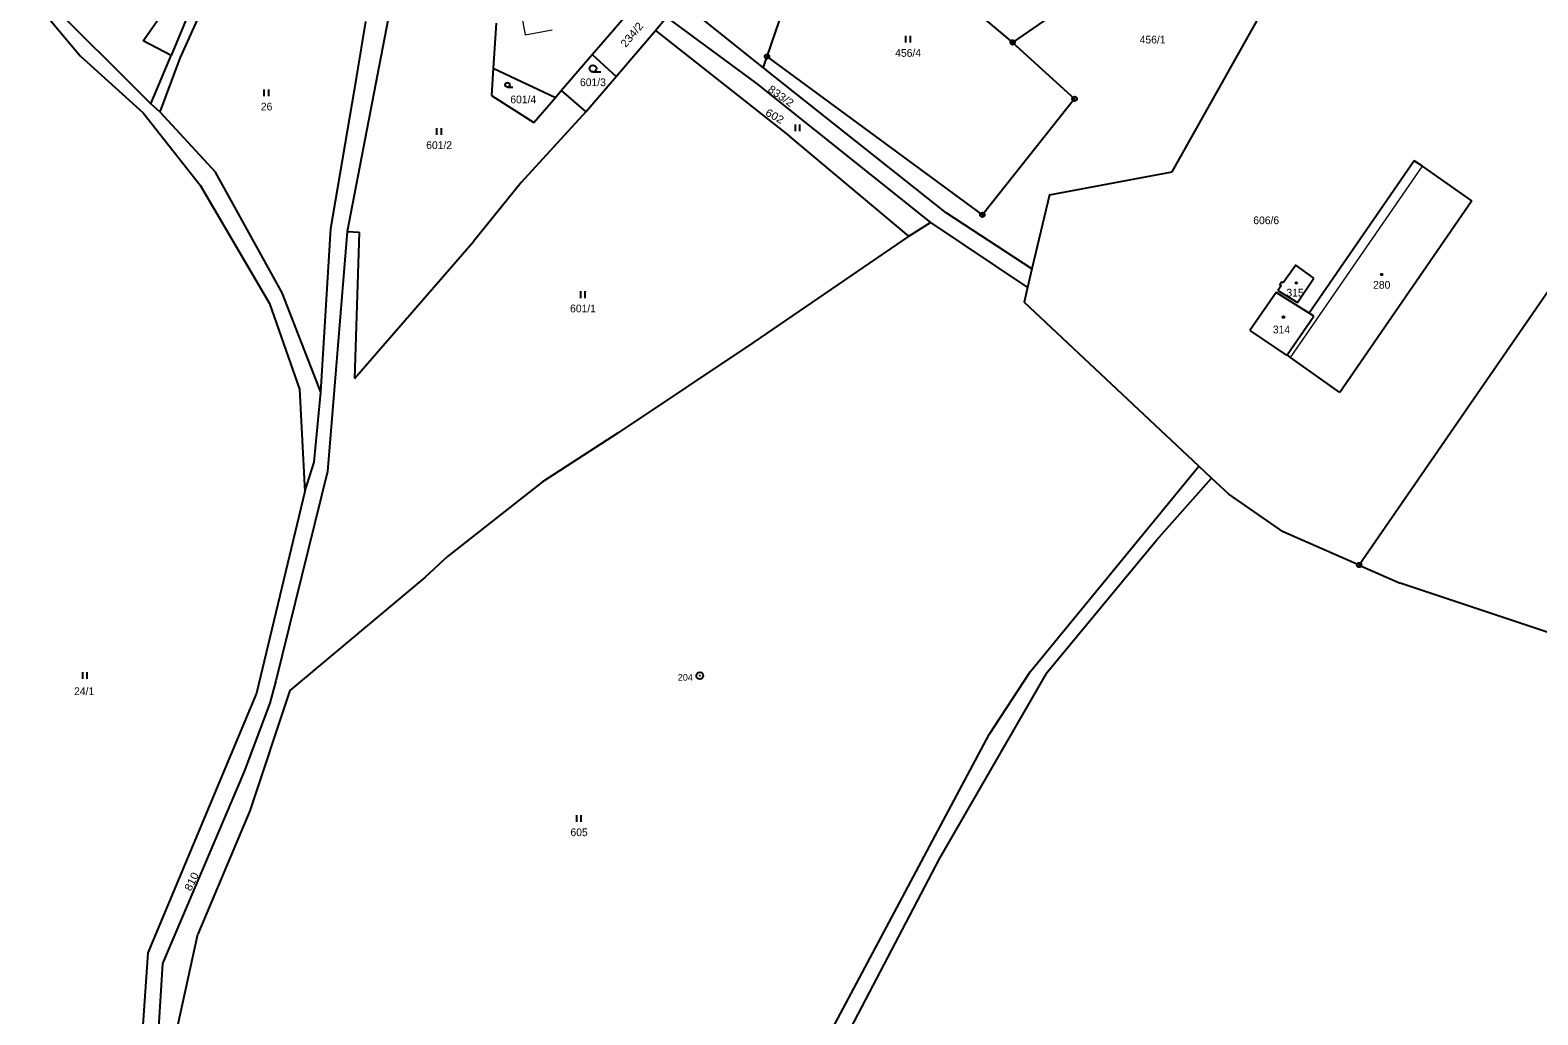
# Model space of a CAD drawing. Extents: x -739410 to -735662, y -942282 to -940043.
# Drawn here: x -737930.6 to -737598.7, y -941824.2 to -941607.4 of the extents above; entities that cross this region are included whole.
import ezdxf
from ezdxf.enums import TextEntityAlignment as Align

# ---------------------------------------------------------------- set-up
doc = ezdxf.new("R2010")
doc.units = 0
doc.header["$LTSCALE"] = 0.68
for name, color, linetype, lineweight in [('1', 7, 'Continuous', 25), ('3', 7, 'Continuous', 25), ('4', 7, 'Continuous', 13), ('5', 7, 'Continuous', 25), ('8', 7, 'Continuous', 25)]:
    doc.layers.add(name, color=color, linetype=linetype, lineweight=lineweight)
doc.layers.add('2', color=7, linetype='Continuous')

msp = doc.modelspace()

# ---------------------------------------------------------------- linework, layer by layer
at = {"layer": '1'}
for p, q in [((-737768.36, -941613.19), (-737755.48, -941575.64)), ((-737755.48, -941575.64), (-737714.29, -941610.09)), ((-737809.88, -941583.11), (-737769.2, -941615.65)), ((-737679.14, -941638.6), (-737649.53, -941585.72)), ((-737682.31, -941587.99), (-737714.29, -941610.09)), ((-737890.94, -941592.16), (-737899.54, -941612.96)), ((-737928.35, -941599.28), (-737904.01, -941623.61)), ((-737890.07, -941596.74), (-737897.59, -941613.54)), ((-737930.57, -941599.84), (-737919.54, -941613.02)), ((-737905.69, -941609.73), (-737899.64, -941601.14)), ((-737851.42, -941603.01), (-737860.8, -941651.75)), ((-737806.88, -941612.78), (-737795.94, -941600.02)), ((-737858.65, -941617.55), (-737856.7, -941605.45)), ((-737827.98, -941605.86), (-737828.62, -941615.79)), ((-737792.88, -941607.48), (-737790.48, -941604.55)), ((-737790.48, -941604.55), (-737770.69, -941619.12)), ((-737801.56, -941617.59), (-737792.88, -941607.48)), ((-737792.88, -941607.48), (-737763.4, -941630.76)), ((-737899.54, -941612.96), (-737905.69, -941609.73)), ((-737904.01, -941623.61), (-737899.54, -941612.96)), ((-737813.65, -941620.67), (-737806.88, -941612.78)), ((-737806.88, -941612.78), (-737801.56, -941617.59)), ((-737714.29, -941610.09), (-737700.65, -941622.51)), ((-737919.54, -941613.02), (-737905.67, -941625.62)), ((-737897.59, -941613.54), (-737902.03, -941625.36)), ((-737828.62, -941615.79), (-737829.01, -941621.79)), ((-737828.62, -941615.79), (-737814.95, -941622.19)), ((-737769.2, -941615.65), (-737768.36, -941613.19)), ((-737769.2, -941615.65), (-737768.71, -941616.05)), ((-737728.94, -941647.58), (-737768.71, -941616.05)), ((-737720.95, -941648.06), (-737768.36, -941613.19)), ((-737864.41, -941651.03), (-737858.65, -941617.55)), ((-737808.26, -941625.37), (-737801.56, -941617.59)), ((-737770.69, -941619.12), (-737732.37, -941649.74)), ((-737829.01, -941621.79), (-737819.72, -941627.75)), ((-737819.72, -941627.75), (-737814.95, -941622.19)), ((-737814.95, -941622.19), (-737813.65, -941620.67)), ((-737813.65, -941620.67), (-737808.26, -941625.37)), ((-737700.65, -941622.51), (-737720.95, -941648.06)), ((-737905.67, -941625.62), (-737893.12, -941641.52)), ((-737902.03, -941625.36), (-737904.01, -941623.61)), ((-737902.03, -941625.36), (-737889.8, -941638.62)), ((-737808.26, -941625.37), (-737822.51, -941640.93)), ((-737737.12, -941652.71), (-737763.4, -941630.76)), ((-737625.86, -941636.15), (-737648.99, -941669.73)), ((-737624.09, -941637.33), (-737625.86, -941636.15)), ((-737875.06, -941665.19), (-737889.8, -941638.62)), ((-737706.2, -941643.64), (-737679.14, -941638.6)), ((-737613.18, -941644.99), (-737624.09, -941637.33)), ((-737893.12, -941641.52), (-737877.89, -941667.56)), ((-737822.51, -941640.93), (-737832.97, -941653.89)), ((-737579.37, -941640.18), (-737637.99, -941725.15)), ((-737706.2, -941643.64), (-737710.06, -941659.94)), ((-737613.18, -941644.99), (-737642.24, -941687.17)), ((-737710.06, -941659.94), (-737728.94, -941647.58)), ((-737866.56, -941687.07), (-737864.41, -941651.03)), ((-737860.8, -941651.75), (-737865.1, -941704.55)), ((-737860.8, -941651.75), (-737858.16, -941651.85)), ((-737858.16, -941651.85), (-737859.14, -941684.08)), ((-737737.12, -941652.71), (-737771.29, -941676.08)), ((-737737.12, -941652.71), (-737732.37, -941649.74)), ((-737732.37, -941649.74), (-737711.02, -941664.04)), ((-737859.14, -941684.08), (-737832.97, -941653.89)), ((-737710.06, -941659.94), (-737711.02, -941664.04)), ((-737651.61, -941667.37), (-737647.95, -941661.97)), ((-737866.56, -941687.07), (-737875.06, -941665.19)), ((-737711.02, -941664.04), (-737711.75, -941667.31)), ((-737656.28, -941665.13), (-737662.08, -941673.54)), ((-737648.99, -941669.73), (-737656.28, -941665.13)), ((-737655.87, -941664.7), (-737651.61, -941667.37)), ((-737654.72, -941663.01), (-737655.05, -941662.78)), ((-737877.89, -941667.56), (-737871.25, -941686.4)), ((-737673.26, -941703.38), (-737711.75, -941667.31)), ((-737647.96, -941670.38), (-737648.99, -941669.73)), ((-737662.08, -941673.54), (-737653.96, -941679.05)), ((-737771.29, -941676.08), (-737801.12, -941696.06)), ((-737653.1, -941679.44), (-737653.86, -941678.9)), ((-737642.24, -941687.17), (-737653.1, -941679.44)), ((-737871.25, -941686.4), (-737870.08, -941708.95)), ((-737868.03, -941702.51), (-737866.56, -941687.07)), ((-737801.12, -941696.06), (-737817.8, -941706.8)), ((-737870.08, -941708.95), (-737868.03, -941702.51)), ((-737865.1, -941704.55), (-737876.52, -941750.61)), ((-737710.42, -941748.66), (-737673.26, -941703.38)), ((-737670.53, -941706.06), (-737673.26, -941703.38)), ((-737870.08, -941708.95), (-737880.72, -941753.34)), ((-737817.8, -941706.8), (-737838.69, -941723.25)), ((-737682.62, -941719.71), (-737670.53, -941706.06)), ((-737666.67, -941709.53), (-737670.53, -941706.06)), ((-737654.74, -941717.82), (-737666.67, -941709.53)), ((-737637.99, -941725.15), (-737654.74, -941717.82)), ((-737706.9, -941749.04), (-737682.62, -941719.71)), ((-737838.69, -941723.25), (-737843.72, -941727.9)), ((-737637.99, -941725.15), (-737628.96, -941729.13)), ((-737843.72, -941727.9), (-737873.42, -941752.76)), ((-737588.31, -941742.69), (-737628.96, -941729.13)), ((-737706.9, -941749.04), (-737730.45, -941789.83)), ((-737719.44, -941762.43), (-737710.42, -941748.66)), ((-737876.52, -941750.61), (-737877.79, -941755.55)), ((-737880.72, -941753.34), (-737904.65, -941810.52)), ((-737877.79, -941755.55), (-737883.46, -941770.59)), ((-737873.42, -941752.76), (-737882.18, -941779.27)), ((-737759.68, -941837.89), (-737719.44, -941762.43)), ((-737883.46, -941770.59), (-737901.42, -941812.86)), ((-737882.18, -941779.27), (-737893.67, -941806.42)), ((-737730.45, -941789.83), (-737757.13, -941840.69)), ((-737899.12, -941831.21), (-737893.67, -941806.42)), ((-737904.65, -941810.52), (-737906.6, -941838.41)), ((-737901.42, -941812.86), (-737902.89, -941835.85))]:
    msp.add_line(p, q, dxfattribs=at)
for points in [[(-737647.95, -941661.97), (-737651.95, -941659.12), (-737654.72, -941663.01)], [(-737655.05, -941662.78), (-737655.5, -941663.44), (-737655.19, -941663.69), (-737655.87, -941664.7)], [(-737653.96, -941679.05), (-737653.86, -941678.9), (-737647.96, -941670.38)]]:
    msp.add_lwpolyline(points, dxfattribs=at)
at = {"layer": '3'}
for p, q in [((-737737.801, -941610.13), (-737737.801, -941608.63)), ((-737736.8, -941610.13), (-737736.8, -941608.63)), ((-737806.673, -941616.59), (-737804.923, -941616.59)), ((-737879.031, -941621.94), (-737879.031, -941620.44)), ((-737878.03, -941621.94), (-737878.03, -941620.44)), ((-737825.475, -941619.92), (-737824.303, -941619.92)), ((-737841.051, -941630.44), (-737841.051, -941628.94)), ((-737840.05, -941630.44), (-737840.05, -941628.94)), ((-737762.111, -941629.66), (-737762.111, -941628.16)), ((-737761.11, -941629.66), (-737761.11, -941628.16)), ((-737809.371, -941666.39), (-737809.371, -941664.89)), ((-737808.37, -941666.39), (-737808.37, -941664.89)), ((-737918.991, -941750.2), (-737918.991, -941748.7)), ((-737917.99, -941750.2), (-737917.99, -941748.7)), ((-737810.241, -941781.71), (-737810.241, -941780.21)), ((-737809.24, -941781.71), (-737809.24, -941780.21))]:
    msp.add_line(p, q, dxfattribs=at)
for centre, radius in [((-737806.6729, -941615.8398), 0.75), ((-737825.4752, -941619.4174), 0.5025)]:
    msp.add_circle(centre, radius, dxfattribs=at)
at = {"layer": '4'}
msp.add_line((-737653.1, -941679.44), (-737624.09, -941637.33), dxfattribs=at)
msp.add_lwpolyline([(-737822.29, -941604.79), (-737821.62, -941608.42), (-737815.67, -941607.3)], dxfattribs=at)
at = {"layer": '5'}
for centre in [(-737633.0368, -941661.1892), (-737651.8468, -941663.0592), (-737654.6668, -941670.5692)]:
    msp.add_circle(centre, 0.175, dxfattribs=at)
at = {"layer": '8'}
for centre, radius in [((-737714.29, -941610.0899), 0.5), ((-737768.36, -941613.1899), 0.5), ((-737714.29, -941610.0899), 0.0303), ((-737768.36, -941613.1899), 0.0303), ((-737700.65, -941622.5099), 0.5), ((-737700.65, -941622.5099), 0.0303), ((-737720.95, -941648.0599), 0.5), ((-737720.95, -941648.0599), 0.0303), ((-737637.99, -941725.1499), 0.5), ((-737637.99, -941725.1499), 0.0303), ((-737783.16, -941749.5098), 0.75), ((-737783.16, -941749.5098), 0.03)]:
    msp.add_circle(centre, radius, dxfattribs=at)

# ---------------------------------------------------------------- texts
at = {"layer": '2', "width": 1.1}
for s, rotation, p in [('234/2', 50, (-737797.4607, -941608.9344)), ('833/2', 325, (-737765.7745, -941622.5716)), ('602', 331, (-737767.0651, -941627.0672)), ('810', 64, (-737894.2845, -941795.2056))]:
    msp.add_text(s, height=1.7, rotation=rotation, dxfattribs=at).set_placement(p, align=Align.CENTER)
at = {"layer": '2'}
for s, p in [('456/1', (-737683.47, -941610.315)), ('456/4', (-737737.29, -941613.255)), ('601/3', (-737806.68, -941619.715)), ('601/4', (-737822.02, -941623.495)), ('26', (-737878.519, -941625.065)), ('601/2', (-737840.54, -941633.565)), ('606/6', (-737658.46, -941650.105)), ('280', (-737633.029, -941664.315)), ('315', (-737652.109, -941666.035)), ('601/1', (-737808.86, -941669.515)), ('314', (-737655.099, -941674.145)), ('24/1', (-737918.689, -941753.775)), ('605', (-737809.729, -941784.835))]:
    msp.add_text(s, height=1.7, dxfattribs=at).set_placement(p, align=Align.CENTER)
at = {"layer": '8'}
msp.add_text('204', height=1.5, dxfattribs=at).set_placement((-737784.659, -941750.627), align=Align.RIGHT)

doc.saveas('drawing.dxf')
